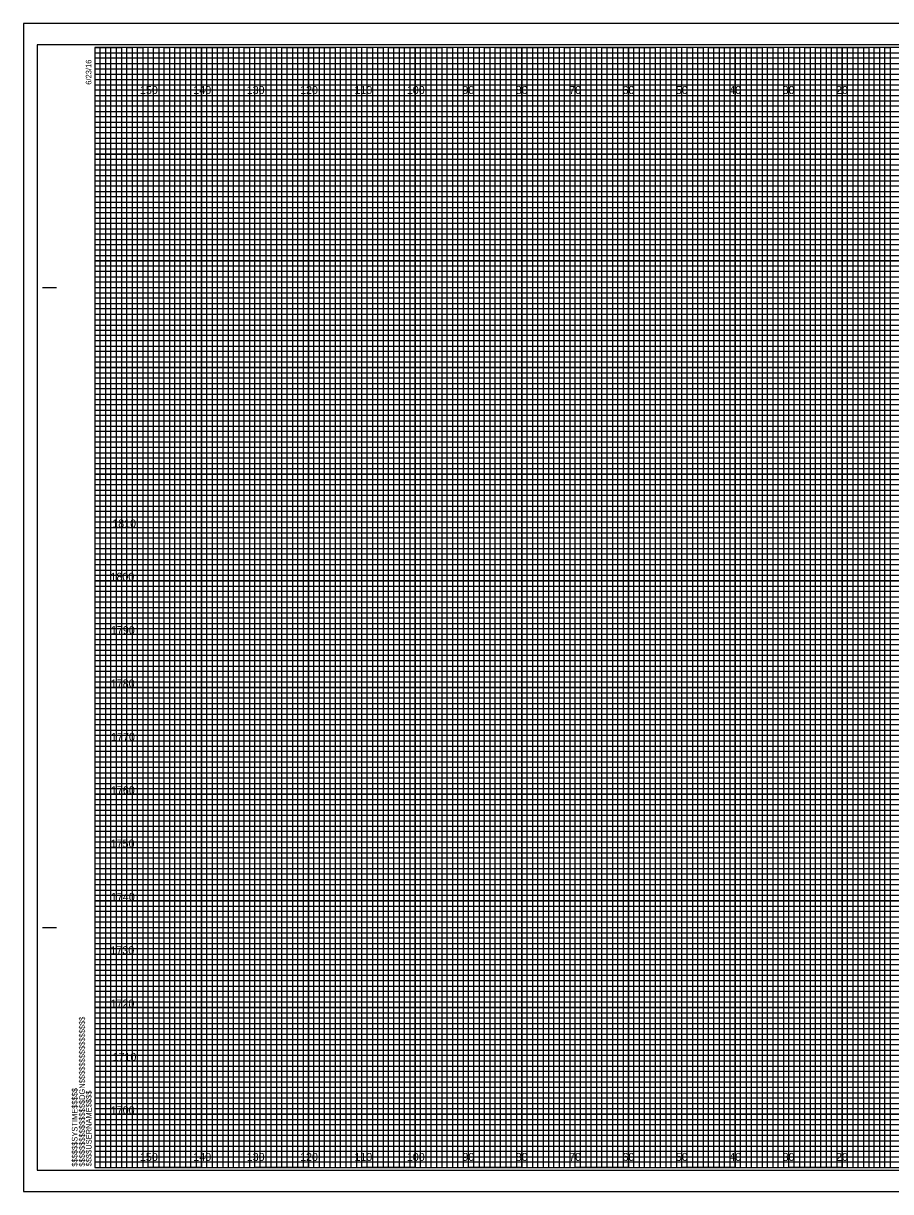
# Model space of a CAD drawing. Extents: x -3334 to 0, y 84 to 12624.
# Drawn here: x -1086.1 to -923.7, y 304.7 to 523.7 of the extents above; entities that cross this region are included whole.
import ezdxf

# ---------------------------------------------------------------- set-up
doc = ezdxf.new("R2010")
doc.units = 0
for name, color, linetype in [('Old_Level_62', 7, 'Continuous'), ('Pattern 1', 7, 'Continuous'), ('Pattern 18', 7, 'Continuous'), ('Pattern 4', 7, 'Continuous'), ('Pattern 5', 7, 'Continuous'), ('Prop Dimension', 7, 'Continuous'), ('Prop Horizontal Alignment', 7, 'Continuous'), ('Raster_Level_0', 7, 'Continuous'), ('Scratch_Level_0', 7, 'Continuous'), ('Scratch_Level_3', 7, 'Continuous'), ('Scratch_Level_5', 7, 'Continuous')]:
    doc.layers.add(name, color=color, linetype=linetype)

msp = doc.modelspace()

# ---------------------------------------------------------------- linework, layer by layer
at = {"layer": 'Old_Level_62'}
for p, q in [((-1082.55, 474.25), (-1080.05, 474.25)), ((-1082.45, 474.25), (-1079.95, 474.25)), ((-1082.55, 354.25), (-1080.05, 354.25)), ((-1082.45, 354.25), (-1079.95, 354.25)), ((-1072.75, 309.25), (-1072.75, 309.25)), ((-1072.75, 309.25), (-1072.75, 309.25)), ((-1072.75, 309.25), (-1072.75, 309.25)), ((-1072.75, 309.25), (-1072.75, 309.25)), ((-1072.75, 309.25), (-1072.75, 309.25)), ((-1072.75, 309.25), (-1072.75, 309.25)), ((-1072.75, 309.25), (-1072.75, 309.25))]:
    msp.add_line(p, q, dxfattribs=at)
msp.add_lwpolyline([(-752.75, 519.25), (-1072.75, 519.25), (-1072.75, 309.25), (-752.75, 309.25)], close=True, dxfattribs=at)
at = {"layer": 'Pattern 18'}
msp.add_lwpolyline([(-1086.15, 304.75), (-749.45, 304.75), (-749.45, 523.75), (-1086.15, 523.75)], close=True, dxfattribs=at)
at = {"layer": 'Pattern 4'}
for p, q in [((-1072.75, 518.25), (-812.75, 518.25)), ((-812.75, 517.23), (-1072.75, 517.23)), ((-1072.75, 517.23), (-1072.75, 516.25)), ((-1072.75, 516.25), (-812.75, 516.25)), ((-812.75, 515.14), (-1072.75, 515.14)), ((-1072.75, 515.14), (-1072.75, 513.25)), ((-1072.75, 513.25), (-752.75, 513.25))]:
    msp.add_line(p, q, dxfattribs=at)
for points in [[(-1072.75, 512.25), (-802.75, 512.25), (-752.75, 512.25), (-752.75, 511.25), (-1072.75, 511.25)], [(-1072.75, 510.25), (-752.75, 510.25), (-752.75, 508.25), (-1072.75, 508.25)], [(-1072.75, 507.25), (-752.75, 507.25), (-752.75, 506.25), (-1072.75, 506.23)], [(-1072.75, 505.25), (-752.75, 505.25), (-752.75, 503.25), (-1072.75, 503.25)], [(-1072.75, 502.25), (-752.75, 502.25), (-752.75, 501.25), (-1072.75, 501.25)], [(-1072.75, 500.25), (-752.75, 500.25), (-752.75, 498.25), (-1072.75, 498.25)], [(-1072.75, 497.25), (-752.75, 497.25), (-752.75, 496.25), (-1072.75, 496.25)], [(-1072.75, 495.25), (-752.75, 495.25), (-752.75, 493.25), (-1072.75, 493.25)], [(-1072.75, 492.25), (-752.75, 492.25), (-752.75, 491.25), (-1072.75, 491.25)], [(-1072.75, 490.25), (-752.75, 490.25), (-752.75, 488.25), (-1072.75, 488.25)], [(-1072.75, 487.25), (-752.75, 487.25), (-752.75, 486.25), (-1072.75, 486.25)], [(-1072.75, 485.25), (-752.75, 485.25), (-752.75, 483.2), (-752.75, 482.25), (-752.75, 481.25), (-1072.75, 481.25)], [(-1072.75, 483.25), (-752.75, 483.25), (-752.75, 482.25), (-1072.75, 482.25)], [(-1072.75, 480.25), (-752.75, 480.25), (-752.75, 478.25), (-1072.75, 478.28)], [(-1072.75, 478.28), (-752.75, 478.25), (-752.75, 477.25), (-1072.75, 477.25)], [(-1072.75, 476.25), (-752.75, 476.25), (-752.75, 475.25), (-1072.75, 475.25)], [(-1072.75, 473.25), (-752.75, 473.25), (-752.75, 472.25), (-1072.75, 472.25)], [(-1072.75, 471.25), (-752.75, 471.25), (-752.75, 470.25), (-1072.75, 470.25)], [(-1072.82, 468.14), (-752.75, 468.14), (-752.75, 467.13), (-1072.82, 467.13)], [(-1072.75, 466.25), (-752.75, 466.25), (-752.75, 465.25), (-1072.75, 465.25)], [(-1072.75, 463.25), (-752.75, 463.25), (-752.75, 462.25), (-1072.75, 462.25)], [(-1072.75, 461.25), (-752.75, 461.25), (-752.75, 460.25), (-1072.75, 460.25)], [(-1072.75, 458.25), (-752.75, 458.25), (-752.75, 457.25), (-1072.75, 457.25)], [(-1072.75, 456.25), (-752.75, 456.25), (-752.75, 455.25), (-1072.75, 455.25)], [(-1072.75, 453.25), (-752.75, 453.25), (-752.75, 452.25), (-1072.75, 452.25)], [(-1072.75, 451.25), (-752.75, 451.25), (-752.75, 450.25), (-1072.75, 450.25)], [(-1072.75, 448.25), (-752.75, 448.25), (-752.76, 447.23), (-1072.75, 447.25)], [(-1072.75, 446.25), (-752.75, 446.25), (-752.75, 445.25), (-1072.75, 445.25)], [(-1072.75, 443.25), (-752.75, 443.25), (-752.75, 442.25), (-1072.75, 442.25)], [(-1072.75, 441.25), (-752.75, 441.25), (-752.75, 440.25), (-1072.75, 440.25)], [(-1072.75, 438.25), (-752.75, 438.25), (-752.75, 437.25), (-1072.75, 437.25)], [(-1072.75, 436.25), (-752.75, 436.25), (-752.75, 435.25), (-1072.75, 435.25)], [(-1072.75, 433.25), (-752.75, 433.25), (-752.75, 432.25), (-1072.75, 432.25)], [(-1072.75, 431.25), (-752.75, 431.25), (-752.75, 430.25), (-1072.75, 430.25)], [(-1072.75, 428.25), (-752.75, 428.25), (-752.75, 427.25), (-1072.75, 427.25)], [(-1072.75, 426.24), (-752.68, 426.16), (-752.75, 425.25), (-1072.75, 425.25)], [(-1072.75, 423.25), (-752.75, 423.25), (-752.75, 422.25), (-1072.75, 422.25)], [(-1072.75, 421.25), (-752.75, 421.25), (-752.75, 420.25), (-1072.75, 420.25)], [(-1072.75, 418.25), (-752.75, 418.25), (-752.75, 417.25), (-1072.75, 417.25)], [(-1072.75, 416.25), (-752.75, 416.25), (-752.75, 415.25), (-1072.75, 415.25)], [(-1072.75, 413.25), (-752.75, 413.25), (-752.75, 412.25), (-1072.75, 412.25)], [(-1072.75, 411.25), (-752.75, 411.25), (-752.75, 410.25), (-1072.75, 410.25)], [(-1072.75, 408.25), (-752.75, 408.25), (-752.75, 407.25), (-1072.75, 407.25)], [(-1072.75, 406.25), (-752.75, 406.25), (-752.75, 405.25), (-1072.75, 405.25)], [(-1072.75, 403.25), (-752.75, 403.25), (-752.75, 402.25), (-1072.75, 402.25)], [(-1072.75, 401.25), (-752.75, 401.25), (-752.75, 400.25), (-1072.75, 400.25)], [(-1072.75, 398.25), (-752.75, 398.25), (-752.75, 397.25), (-1072.75, 397.25)], [(-1072.75, 396.25), (-752.75, 396.25), (-752.75, 395.25), (-1072.75, 395.25)], [(-1072.75, 393.25), (-752.75, 393.25), (-752.75, 392.25), (-1072.75, 392.25)], [(-1072.75, 391.25), (-752.75, 391.25), (-752.75, 390.25), (-1072.75, 390.25)], [(-1072.75, 388.25), (-752.75, 388.25), (-752.76, 387.23), (-1072.75, 387.25)], [(-1072.75, 386.25), (-752.75, 386.25), (-752.75, 385.25), (-1072.75, 385.25)], [(-1072.75, 383.25), (-752.75, 383.25), (-752.75, 382.25), (-1072.75, 382.25)], [(-1072.75, 381.25), (-752.75, 381.25), (-752.75, 380.25), (-1072.75, 380.25)], [(-1072.75, 378.25), (-752.75, 378.25), (-752.75, 377.25), (-1072.75, 377.25)], [(-1072.75, 376.25), (-752.75, 376.25), (-752.75, 375.25), (-1072.75, 375.25)], [(-1072.75, 373.25), (-752.75, 373.25), (-752.75, 372.25), (-1072.75, 372.25)], [(-1072.75, 371.25), (-752.75, 371.25), (-752.75, 370.25), (-1072.75, 370.25)], [(-1072.75, 368.25), (-752.75, 368.25), (-752.75, 367.25), (-1072.75, 367.25)], [(-1072.75, 366.24), (-752.68, 366.16), (-752.75, 365.25), (-1072.75, 365.25)], [(-1072.75, 363.25), (-752.75, 363.25), (-752.75, 362.25), (-1072.75, 362.25)], [(-1072.75, 361.25), (-752.75, 361.25), (-752.75, 360.25), (-1072.75, 360.25)], [(-1072.75, 358.25), (-752.75, 358.25), (-752.75, 357.25), (-1072.75, 357.25)], [(-1072.75, 356.25), (-752.75, 356.25), (-752.75, 355.25), (-1072.75, 355.25)], [(-1072.75, 353.25), (-752.75, 353.25), (-752.75, 352.25), (-1072.75, 352.25)], [(-1072.75, 351.25), (-752.75, 351.25), (-752.75, 350.25), (-1072.75, 350.25)], [(-1072.75, 348.25), (-752.75, 348.25), (-752.75, 347.25), (-1072.75, 347.25)], [(-1072.75, 346.25), (-752.75, 346.25), (-752.75, 345.25), (-1072.75, 345.25)], [(-1072.75, 343.25), (-752.75, 343.25), (-752.75, 342.25), (-1072.75, 342.25)], [(-1072.75, 341.25), (-752.75, 341.25), (-752.75, 340.25), (-1072.75, 340.25)], [(-1072.75, 338.25), (-752.75, 338.25), (-752.75, 337.25), (-1072.75, 337.25)], [(-1072.75, 336.25), (-752.75, 336.25), (-752.75, 335.25), (-1072.75, 335.25)], [(-1072.75, 333.25), (-752.75, 333.25), (-752.75, 332.25), (-1072.75, 332.25)], [(-1072.75, 331.25), (-752.75, 331.25), (-752.75, 330.25), (-1072.75, 330.25)], [(-1072.75, 328.25), (-752.75, 328.25), (-752.75, 327.25), (-1072.75, 327.25)], [(-1072.75, 326.25), (-752.75, 326.25), (-752.75, 325.25), (-1072.75, 325.25)], [(-1072.75, 323.25), (-752.75, 323.25), (-752.75, 322.25), (-1072.75, 322.25)], [(-1072.75, 321.25), (-752.75, 321.25), (-752.75, 320.25), (-1072.75, 320.25)], [(-1072.75, 318.25), (-752.75, 318.25), (-752.75, 317.25), (-1072.75, 317.25)], [(-1072.75, 316.25), (-752.75, 316.25), (-752.75, 315.25), (-1072.75, 315.25)], [(-1072.75, 313.25), (-752.75, 313.25), (-752.75, 312.25), (-1072.75, 312.25)], [(-1072.75, 311.25), (-752.75, 311.25), (-752.75, 310.25), (-1072.75, 310.25)]]:
    msp.add_lwpolyline(points, dxfattribs=at)
at = {"layer": 'Pattern 5'}
for p, q in [((-749.45, 523.75), (-1086.15, 523.75)), ((-1086.15, 523.75), (-1086.15, 304.75)), ((-1086.15, 304.75), (-749.45, 304.75))]:
    msp.add_line(p, q, dxfattribs=at)
at = {"layer": 'Prop Dimension'}
for points in [[(-1072.75, 309.25), (-1071.75, 309.25), (-1071.75, 519.25), (-1070.75, 519.25), (-1070.75, 309.25)], [(-1070.75, 309.25), (-1069.75, 309.25), (-1069.75, 519.25), (-1068.75, 519.25), (-1068.75, 309.25)], [(-1067.75, 309.25), (-1066.75, 309.25), (-1066.75, 519.25), (-1065.75, 519.25), (-1065.75, 309.25)], [(-1065.75, 309.25), (-1064.75, 309.25), (-1064.75, 519.25), (-1063.75, 519.25), (-1063.75, 309.25)], [(-1062.75, 309.25), (-1061.75, 309.25), (-1061.75, 519.25), (-1060.75, 519.25), (-1060.75, 309.25)], [(-1060.75, 309.25), (-1059.75, 309.25), (-1059.75, 519.25), (-1058.75, 519.25), (-1058.75, 309.25)], [(-1057.75, 309.25), (-1056.75, 309.25), (-1056.75, 519.25), (-1055.75, 519.25), (-1055.75, 309.25)], [(-1055.75, 309.25), (-1054.75, 309.25), (-1054.75, 519.25), (-1053.75, 519.25), (-1053.75, 309.25)], [(-1052.75, 309.25), (-1051.75, 309.25), (-1051.75, 519.25), (-1050.75, 519.25), (-1050.75, 309.25)], [(-1050.75, 309.25), (-1049.75, 309.25), (-1049.75, 519.25), (-1048.75, 519.25), (-1048.75, 309.25)], [(-1047.75, 309.25), (-1046.75, 309.25), (-1046.75, 519.25), (-1045.75, 519.25), (-1045.75, 309.25)], [(-1045.75, 309.25), (-1044.75, 309.25), (-1044.75, 519.25), (-1043.75, 519.25), (-1043.75, 309.25)], [(-1042.75, 309.25), (-1041.75, 309.25), (-1041.75, 519.25), (-1040.75, 519.25), (-1040.75, 309.25)], [(-1040.75, 309.25), (-1039.75, 309.25), (-1039.75, 519.25), (-1038.75, 519.25), (-1038.75, 309.25)], [(-1037.75, 309.25), (-1036.75, 309.25), (-1036.75, 519.25), (-1035.75, 519.25), (-1035.75, 309.25)], [(-1035.75, 309.25), (-1034.75, 309.25), (-1034.75, 519.25), (-1033.75, 519.25), (-1033.75, 309.25)], [(-1032.75, 309.25), (-1031.75, 309.25), (-1031.75, 519.25), (-1030.75, 519.25), (-1030.75, 309.25)], [(-1030.75, 309.25), (-1029.75, 309.25), (-1029.75, 519.25), (-1028.75, 519.25), (-1028.75, 309.25)], [(-1027.75, 309.25), (-1026.75, 309.25), (-1026.75, 519.25), (-1025.75, 519.25), (-1025.75, 309.25)], [(-1025.75, 309.25), (-1024.75, 309.25), (-1024.75, 519.25), (-1023.75, 519.25), (-1023.75, 309.25)], [(-1022.75, 309.25), (-1021.75, 309.25), (-1021.75, 519.25), (-1020.75, 519.25), (-1020.75, 309.25)], [(-1020.75, 309.25), (-1019.75, 309.25), (-1019.75, 519.25), (-1018.75, 519.25), (-1018.75, 309.25)], [(-1017.75, 309.25), (-1016.75, 309.25), (-1016.75, 519.25), (-1015.75, 519.25), (-1015.75, 309.25)], [(-1015.75, 309.25), (-1014.75, 309.25), (-1014.75, 519.25), (-1013.75, 519.25), (-1013.75, 309.25)], [(-1012.75, 309.25), (-1011.75, 309.25), (-1011.75, 519.25), (-1010.75, 519.25), (-1010.75, 309.25)], [(-1010.75, 309.25), (-1009.75, 309.25), (-1009.75, 519.25), (-1008.75, 519.25), (-1008.75, 309.25)], [(-1007.75, 309.25), (-1006.75, 309.25), (-1006.75, 519.25), (-1005.75, 519.25), (-1005.75, 309.25)], [(-1005.75, 309.25), (-1004.75, 309.25), (-1004.75, 519.25), (-1003.75, 519.25), (-1003.75, 309.25)], [(-1002.75, 309.25), (-1001.75, 309.25), (-1001.75, 519.25), (-1000.75, 519.25), (-1000.75, 309.25)], [(-1000.75, 309.25), (-999.75, 309.25), (-999.75, 519.25), (-998.75, 519.25), (-998.75, 309.25)], [(-997.75, 309.25), (-996.75, 309.25), (-996.75, 519.25), (-995.75, 519.25), (-995.75, 309.25)], [(-995.75, 309.25), (-994.75, 309.25), (-994.75, 519.25), (-993.75, 519.25), (-993.75, 309.25)], [(-992.75, 309.25), (-991.75, 309.25), (-991.75, 519.25), (-990.75, 519.25), (-990.75, 309.25)], [(-990.75, 309.25), (-989.75, 309.25), (-989.75, 519.25), (-988.75, 519.25), (-988.75, 309.25)], [(-987.75, 309.25), (-986.75, 309.25), (-986.75, 519.25), (-985.75, 519.25), (-985.75, 309.25)], [(-985.75, 309.25), (-984.75, 309.25), (-984.75, 519.25), (-983.75, 519.25), (-983.75, 309.25)], [(-982.75, 309.25), (-981.75, 309.25), (-981.75, 519.25), (-980.75, 519.25), (-980.75, 309.25)], [(-980.75, 309.25), (-979.75, 309.25), (-979.75, 519.25), (-978.75, 519.25), (-978.75, 309.25)], [(-977.75, 309.25), (-976.75, 309.25), (-976.75, 519.25), (-975.75, 519.25), (-975.75, 309.25)], [(-975.75, 309.25), (-974.75, 309.25), (-974.75, 519.25), (-973.75, 519.25), (-973.75, 309.25)], [(-972.75, 309.25), (-971.75, 309.25), (-971.75, 519.25), (-970.75, 519.25), (-970.75, 309.25)], [(-970.75, 309.25), (-969.75, 309.25), (-969.75, 519.25), (-968.75, 519.25), (-968.75, 309.25)], [(-967.75, 309.25), (-966.75, 309.25), (-966.75, 519.25), (-965.75, 519.25), (-965.75, 309.25)], [(-965.75, 309.25), (-964.75, 309.25), (-964.75, 519.25), (-963.75, 519.25), (-963.75, 309.25)], [(-962.75, 309.25), (-961.75, 309.25), (-961.75, 519.25), (-960.75, 519.25), (-960.75, 309.25)], [(-960.75, 309.25), (-959.75, 309.25), (-959.75, 519.25), (-958.75, 519.25), (-958.75, 309.25)], [(-957.75, 309.25), (-956.75, 309.25), (-956.75, 519.25), (-955.75, 519.25), (-955.75, 309.25)], [(-955.75, 309.25), (-954.75, 309.25), (-954.75, 519.25), (-953.75, 519.25), (-953.75, 309.25)], [(-952.75, 309.25), (-951.75, 309.25), (-951.75, 519.25), (-950.75, 519.25), (-950.75, 309.25)], [(-950.75, 309.25), (-949.75, 309.25), (-949.75, 519.25), (-948.75, 519.25), (-948.75, 309.25)], [(-947.75, 309.25), (-946.75, 309.25), (-946.75, 519.25), (-945.75, 519.25), (-945.75, 309.25)], [(-945.75, 309.25), (-944.75, 309.25), (-944.75, 519.25), (-943.75, 519.25), (-943.75, 309.25)], [(-942.75, 309.25), (-941.75, 309.25), (-941.75, 519.25), (-940.75, 519.25), (-940.75, 309.25)], [(-940.75, 309.25), (-939.75, 309.25), (-939.75, 519.25), (-938.75, 519.25), (-938.75, 309.25)], [(-937.75, 309.25), (-936.75, 309.25), (-936.75, 519.25), (-935.75, 519.25), (-935.75, 309.25)], [(-935.75, 309.25), (-934.75, 309.25), (-934.75, 519.25), (-933.75, 519.25), (-933.75, 309.25)], [(-932.75, 309.25), (-931.75, 309.25), (-931.75, 519.25), (-930.75, 519.25), (-930.75, 309.25)], [(-930.75, 309.25), (-929.75, 309.25), (-929.75, 519.25), (-928.75, 519.25), (-928.75, 309.25)], [(-927.75, 309.25), (-926.75, 309.25), (-926.75, 519.25), (-925.75, 519.25), (-925.75, 309.25)], [(-925.75, 309.25), (-924.75, 309.25), (-924.75, 519.25), (-923.75, 519.25), (-923.75, 309.25)]]:
    msp.add_lwpolyline(points, dxfattribs=at)
at = {"layer": 'Prop Horizontal Alignment'}
for points in [[(-1072.75, 519.25), (-1067.75, 519.25), (-1067.75, 309.25), (-1057.75, 309.25), (-1057.75, 519.25), (-1047.75, 519.25), (-1047.75, 309.25), (-1037.75, 309.25), (-1037.75, 519.25), (-1027.75, 519.25), (-1027.75, 309.25), (-1017.75, 309.25), (-1017.75, 519.25), (-1007.75, 519.25), (-1007.75, 309.25), (-997.75, 309.25), (-997.75, 519.25), (-987.75, 519.25), (-987.75, 309.25), (-977.75, 309.25), (-977.75, 519.25), (-967.75, 519.25), (-967.75, 309.25), (-957.75, 309.25), (-957.75, 519.25), (-947.75, 519.25), (-947.75, 309.25), (-937.75, 309.25), (-937.75, 519.25), (-927.75, 519.25), (-927.75, 309.25), (-917.75, 309.25)], [(-1072.75, 514.25), (-797.75, 514.25)], [(-1072.75, 494.25), (-752.75, 494.25), (-752.75, 504.25), (-1072.75, 504.25)], [(-1072.75, 474.25), (-752.75, 474.25), (-752.75, 484.25), (-1072.75, 484.25)], [(-1072.75, 454.25), (-752.75, 454.25), (-752.75, 464.25), (-1072.75, 464.25)], [(-1072.75, 434.25), (-752.75, 434.25), (-752.75, 444.25), (-1072.75, 444.25)], [(-1072.75, 414.25), (-752.75, 414.25), (-752.75, 424.25), (-1072.75, 424.25)], [(-1072.75, 394.25), (-752.75, 394.25), (-752.75, 404.25), (-1072.75, 404.25)], [(-1072.75, 374.25), (-752.75, 374.25), (-752.75, 384.25), (-1072.75, 384.25)], [(-1072.75, 354.25), (-752.75, 354.25), (-752.75, 364.25), (-1072.75, 364.25)], [(-1072.75, 334.25), (-752.75, 334.25), (-752.75, 344.25), (-1072.75, 344.25)], [(-1072.75, 314.25), (-752.75, 314.25), (-752.75, 324.25), (-1072.75, 324.25)]]:
    msp.add_lwpolyline(points, dxfattribs=at)
at = {"layer": 'Scratch_Level_0'}
for p, q in [((-1062.75, 309.25), (-1062.75, 519.25)), ((-1052.75, 309.25), (-1052.75, 519.25)), ((-1042.75, 309.25), (-1042.75, 519.25)), ((-1032.75, 309.25), (-1032.75, 519.25)), ((-1022.75, 309.25), (-1022.75, 519.25)), ((-1012.75, 309.25), (-1012.75, 519.25)), ((-1002.75, 309.25), (-1002.75, 519.25)), ((-992.75, 309.25), (-992.75, 519.25)), ((-982.75, 309.25), (-982.75, 519.25)), ((-972.75, 309.25), (-972.75, 519.25)), ((-962.75, 309.25), (-962.75, 519.25)), ((-952.75, 309.25), (-952.75, 519.25)), ((-942.75, 309.25), (-942.75, 519.25)), ((-932.75, 309.25), (-932.75, 519.25)), ((-1072.75, 509.25), (-752.75, 509.25)), ((-1072.75, 499.25), (-752.75, 499.25)), ((-1072.75, 489.25), (-752.75, 489.25)), ((-1072.75, 479.25), (-752.75, 479.25)), ((-1072.75, 469.25), (-752.75, 469.25)), ((-1072.75, 459.25), (-752.75, 459.25)), ((-1072.75, 449.25), (-752.75, 449.25)), ((-1072.75, 439.25), (-752.75, 439.25)), ((-1072.75, 429.25), (-752.75, 429.25)), ((-1072.75, 419.25), (-752.75, 419.25)), ((-1072.75, 409.25), (-752.75, 409.25)), ((-1072.75, 399.25), (-752.75, 399.25)), ((-1072.75, 389.25), (-752.75, 389.25)), ((-1072.75, 379.25), (-752.75, 379.25)), ((-1072.75, 369.25), (-752.75, 369.25)), ((-1072.75, 359.25), (-752.75, 359.25)), ((-1072.75, 349.25), (-752.75, 349.25)), ((-1072.75, 339.25), (-752.75, 339.25)), ((-1072.75, 329.25), (-752.75, 329.25)), ((-1072.75, 319.25), (-752.75, 319.25))]:
    msp.add_line(p, q, dxfattribs=at)
at = {"layer": 'Scratch_Level_3'}
for p, q in [((-1062.75, 519.25), (-1072.75, 519.25)), ((-1062.75, 309.25), (-1062.75, 519.25)), ((-1042.75, 519.25), (-1052.75, 519.25)), ((-1052.75, 519.25), (-1052.75, 309.25)), ((-1042.75, 309.25), (-1042.75, 519.25)), ((-1022.75, 519.25), (-1032.75, 519.25)), ((-1032.75, 519.25), (-1032.75, 309.25)), ((-1022.75, 309.25), (-1022.75, 519.25)), ((-1002.75, 519.25), (-1012.75, 519.25)), ((-1012.75, 519.25), (-1012.75, 309.25)), ((-1002.75, 309.25), (-1002.75, 519.25)), ((-982.75, 519.25), (-992.75, 519.25)), ((-992.75, 519.25), (-992.75, 309.25)), ((-982.75, 309.25), (-982.75, 519.25)), ((-962.75, 519.25), (-972.75, 519.25)), ((-972.75, 519.25), (-972.75, 309.25)), ((-962.75, 309.25), (-962.75, 519.25)), ((-942.75, 519.25), (-952.75, 519.25)), ((-952.75, 519.25), (-952.75, 309.25)), ((-942.75, 309.25), (-942.75, 519.25)), ((-922.75, 519.25), (-932.75, 519.25)), ((-932.75, 519.25), (-932.75, 309.25)), ((-1052.75, 309.25), (-1062.75, 309.25)), ((-1032.75, 309.25), (-1042.75, 309.25)), ((-1012.75, 309.25), (-1022.75, 309.25)), ((-992.75, 309.25), (-1002.75, 309.25)), ((-972.75, 309.25), (-982.75, 309.25)), ((-952.75, 309.25), (-962.75, 309.25)), ((-932.75, 309.25), (-942.75, 309.25))]:
    msp.add_line(p, q, dxfattribs=at)
for points in [[(-1072.75, 509.25), (-752.75, 509.25), (-752.75, 499.25), (-1072.75, 499.25)], [(-1072.75, 489.25), (-752.75, 489.25), (-752.75, 479.25), (-1072.75, 479.25)], [(-1072.75, 469.25), (-752.75, 469.25), (-752.75, 459.25), (-1072.75, 459.25)], [(-1072.75, 449.25), (-752.75, 449.25), (-752.75, 439.25), (-1072.75, 439.25)], [(-1072.75, 429.25), (-752.75, 429.25), (-752.75, 419.25), (-1072.75, 419.25)], [(-1072.75, 409.25), (-752.75, 409.25), (-752.75, 399.25), (-1072.75, 399.25)], [(-1072.75, 389.25), (-752.75, 389.25), (-752.75, 379.25), (-1072.75, 379.25)], [(-1072.75, 369.25), (-752.75, 369.25), (-752.75, 359.25), (-1072.75, 359.25)], [(-1072.75, 349.25), (-752.75, 349.25), (-752.75, 339.25), (-1072.75, 339.25)], [(-1072.75, 329.25), (-752.75, 329.25), (-752.75, 319.25), (-1072.75, 319.25)]]:
    msp.add_lwpolyline(points, dxfattribs=at)
at = {"layer": 'Scratch_Level_5'}
msp.add_lwpolyline([(-1083.55, 308.75), (-750.35, 308.75), (-750.35, 519.75), (-1083.55, 519.75)], close=True, dxfattribs=at)

# ---------------------------------------------------------------- texts
at = {"layer": 'Old_Level_62'}
for s, p in [('6/23/16', (-1073.4, 512.25)), ('$$$$$$$$$$$$$$$$DGN$$$$$$$$$$$$$$$$', (-1074.63, 309.43)), ('$$$$$$SYSTIME$$$$$', (-1076.01, 309.43)), ('$$$$USERNAME$$$$', (-1073.37, 309.48))]:
    msp.add_text(s, height=1.05, rotation=90, dxfattribs=at).set_placement(p)
at = {"layer": 'Pattern 1'}
for s, p in [('1810', (-1069.5, 429.25)), ('1800', (-1069.83, 419.25)), ('1790', (-1069.74, 409.25)), ('1780', (-1069.77, 399.25)), ('1770', (-1069.71, 389.25)), ('1760', (-1069.74, 379.25)), ('1750', (-1069.79, 369.25)), ('1740', (-1069.74, 359.25)), ('1730', (-1069.83, 349.25)), ('1720', (-1069.81, 339.25)), ('1710', (-1069.44, 329.25)), ('1700', (-1069.77, 319.25))]:
    msp.add_text(s, height=1.5, dxfattribs=at).set_placement(p)
at = {"layer": 'Raster_Level_0'}
for s, p in [('150', (-1064.3, 510.5)), ('140', (-1054.3, 510.5)), ('130', (-1044.3, 510.5)), ('120', (-1034.3, 510.5)), ('110', (-1024.12, 510.5)), ('100', (-1014.3, 510.5)), ('90', (-1003.89, 510.5)), ('80', (-993.89, 510.5)), ('70', (-983.89, 510.5)), ('60', (-973.89, 510.5)), ('50', (-963.89, 510.5)), ('40', (-953.89, 510.5)), ('30', (-943.89, 510.5)), ('20', (-933.89, 510.5)), ('150', (-1064.3, 310.5)), ('140', (-1054.3, 310.5)), ('130', (-1044.3, 310.5)), ('120', (-1034.3, 310.5)), ('110', (-1024.12, 310.5)), ('100', (-1014.3, 310.5)), ('90', (-1003.89, 310.5)), ('80', (-993.89, 310.5)), ('70', (-983.89, 310.5)), ('60', (-973.89, 310.5)), ('50', (-963.89, 310.5)), ('40', (-953.89, 310.5)), ('30', (-943.89, 310.5)), ('20', (-933.89, 310.5))]:
    msp.add_text(s, height=1.5, dxfattribs=at).set_placement(p)

doc.saveas('drawing.dxf')
